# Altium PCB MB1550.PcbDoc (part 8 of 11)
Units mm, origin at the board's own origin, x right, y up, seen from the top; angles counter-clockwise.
Board outline 154.81 x 170.69 mm, 6 copper layers (Top Layer, Signal Layer 1, Signal Layer 2, Signal Layer 3, Signal Layer 4, Bottom Layer), stack 1.49 mm thick; 810 components, 633 nets, 2973 pads, 2150 vias.
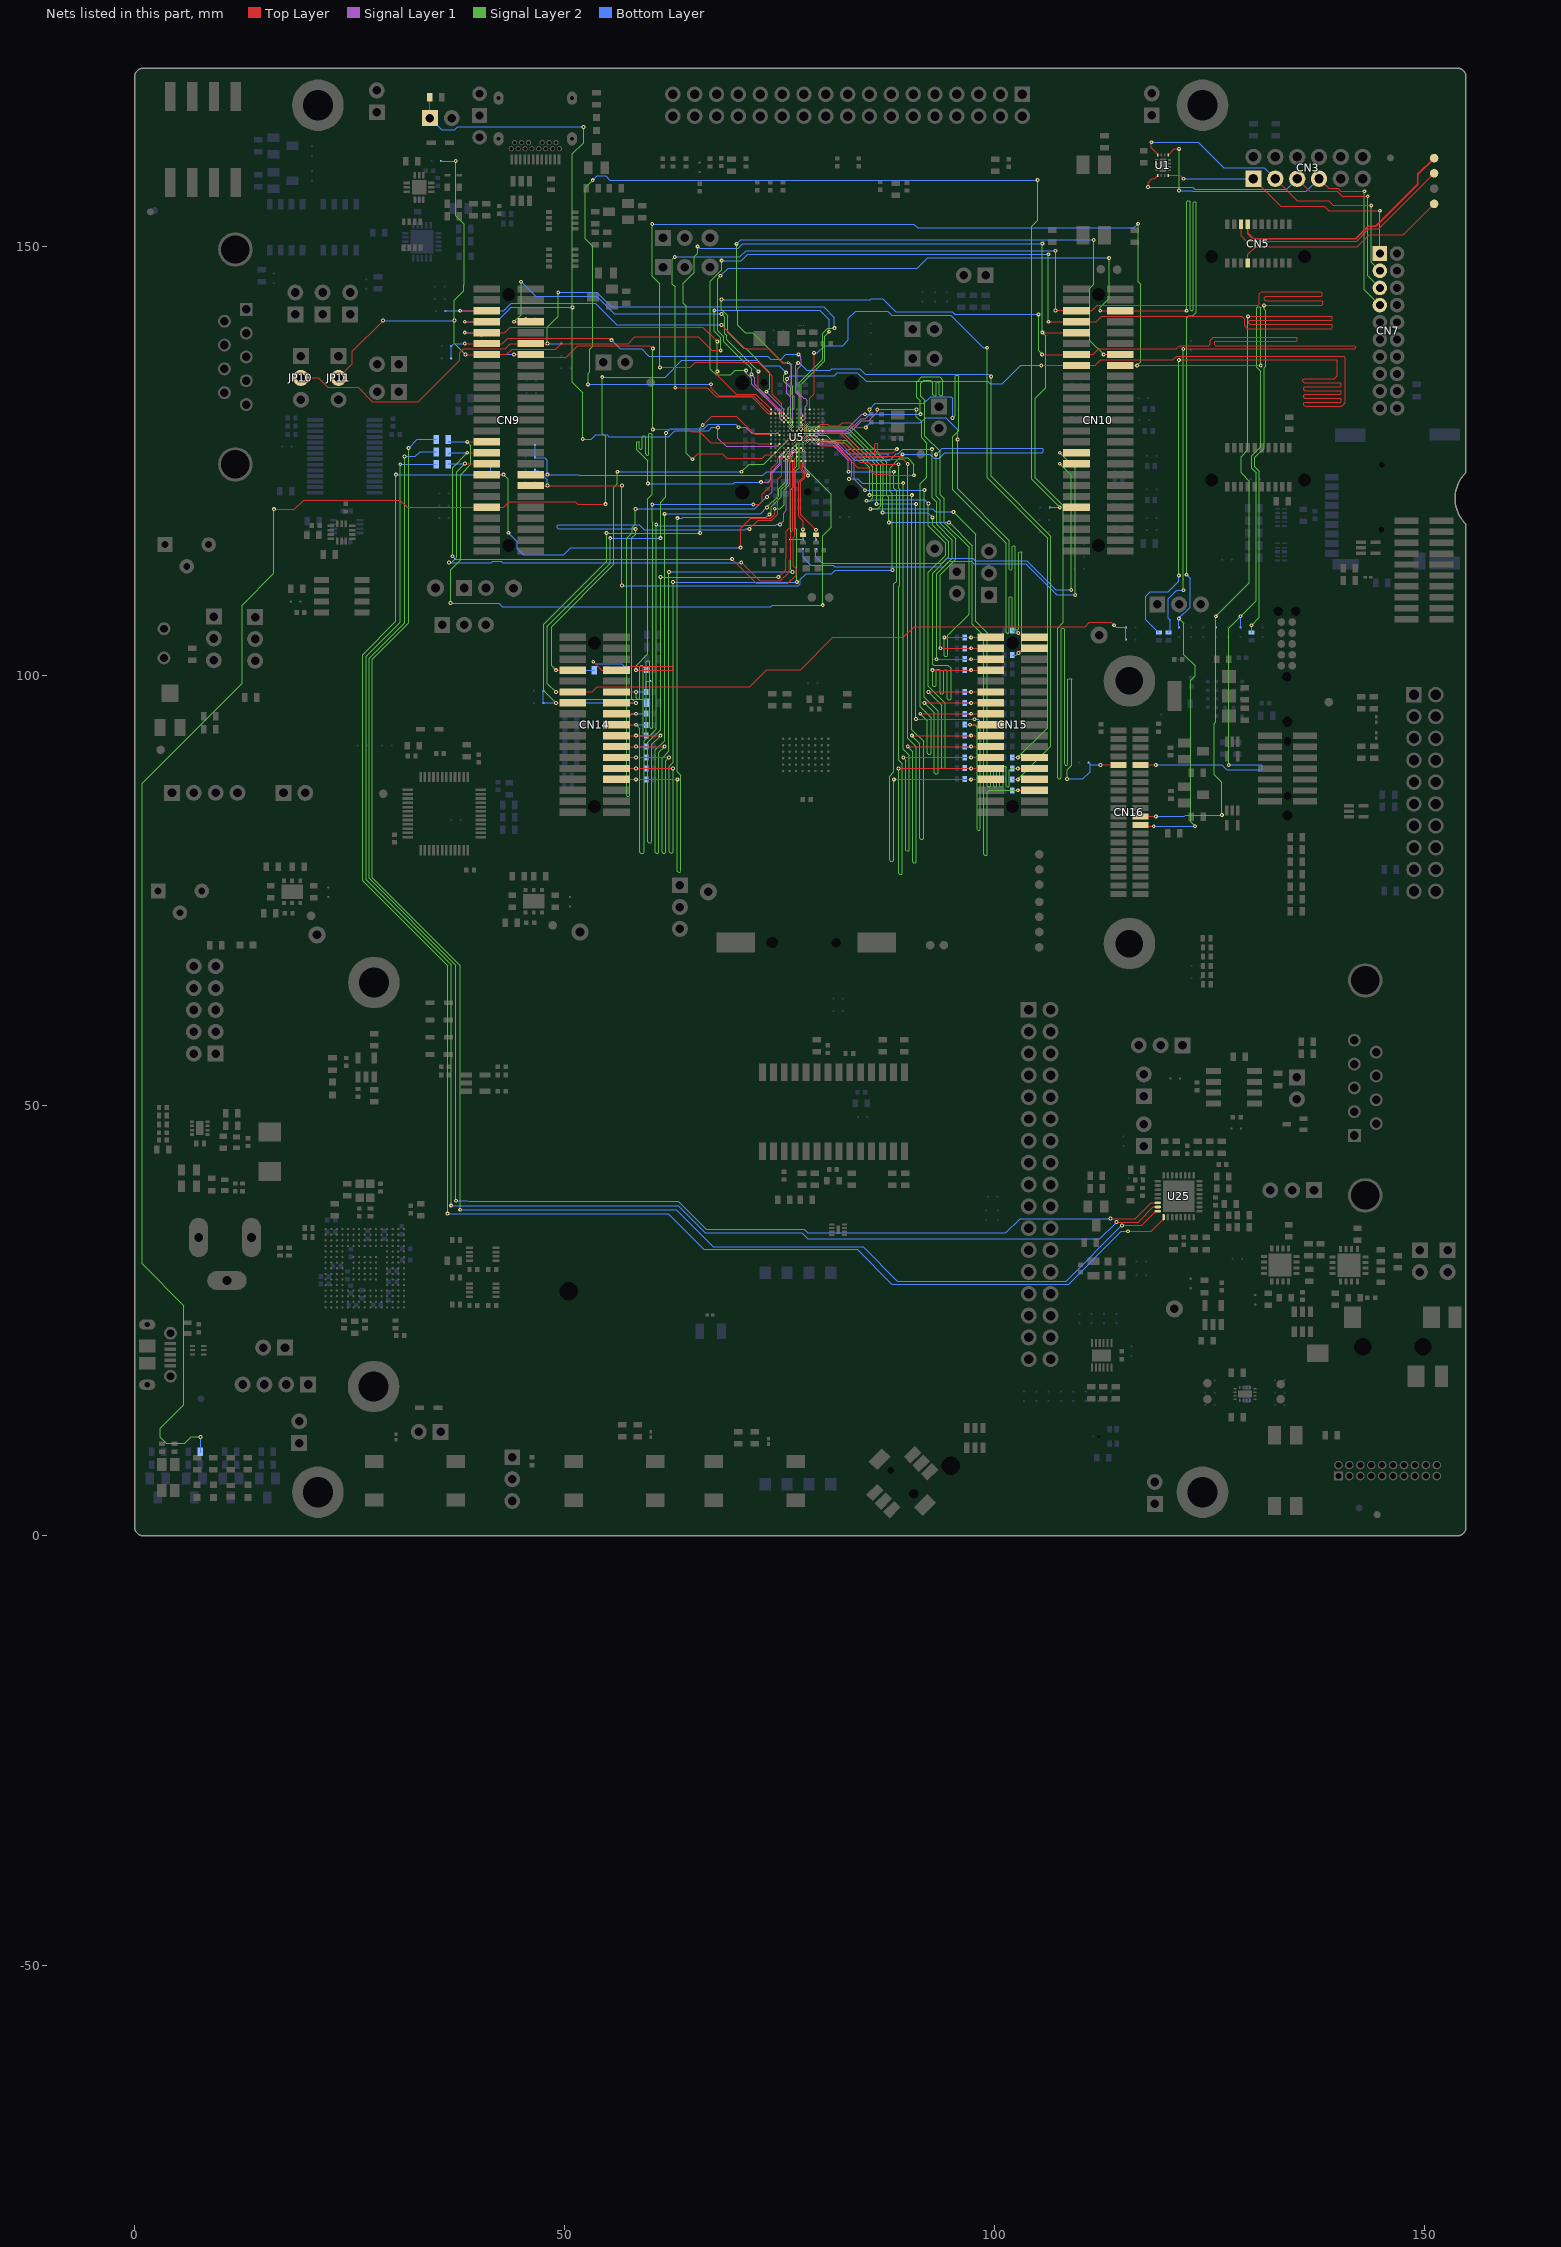
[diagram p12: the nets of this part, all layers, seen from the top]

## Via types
v1: diameter 0.45, hole 0.2, Top Layer to Bottom Layer, tented both sides, 1777 vias
v2: diameter 0.25, hole 0.1, Top Layer to Signal Layer 1, tented top, 344 vias
v3: diameter 0.25, hole 0.1, Signal Layer 1 to Signal Layer 2, 29 vias

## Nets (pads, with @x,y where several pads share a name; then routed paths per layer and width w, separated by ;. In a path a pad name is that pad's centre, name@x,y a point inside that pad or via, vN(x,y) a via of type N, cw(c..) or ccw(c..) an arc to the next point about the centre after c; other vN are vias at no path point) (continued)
PE3: CN14.8 R189.2 U5.D3 | length 81.7
  Top Layer w0.1: v1(53.325,101.65) 54.295,100.68 CN14.8@56.025,100.68 57.155,100.68 57.625,101.15 62.575,101.15 62.65,101.075 62.65,100.8 62.53,100.68 v1(58.295,100.68) ; v2(75.25,125.75) U5.D3@75.5,126
  Signal Layer 1 w0.08: v1(72.842,122.536) 73.686,122.536 73.95,122.8 73.95,123.65 75.035,124.735 75.035,125.434 75.25,125.649 v2(75.25,125.75)
  Signal Layer 2 w0.09: v1(58.295,100.68) 58.295,101.195 59.675,102.575 59.675,120.625 60.175,121.125 60.175,128.05 60.025,128.2 59.85,128.2 59.75,128.1 59.75,125.75 59.675,125.675 59.55,125.675 59.4,125.825 59.4,127.85 59.325,127.925 59.119,127.925 59.025,127.831 59.025,126.468 58.925,126.368 58.79,126.368 58.685,126.473 58.685,127.203 58.643,127.245 58.435,127.245 58.382,127.193 58.382,126.293 59.675,125 v1(59.675,122.372)
  Bottom Layer w0.1: v1(53.325,101.65) 53.525,101.45 56.625,101.45 56.925,101.15 59.025,101.15 59.475,100.7 R189.2@59.475,100.675 ; v1(59.675,122.372) 69.625,122.372 69.789,122.536 v1(72.842,122.536)
PE4: CN14.12 R191.1 SB105.1 U5.C2 | length 80.9
  Top Layer w0.08: 74.6,124.7 74.75,124.85 74.75,125.104 74.75,125.25 U5.C2@75,125.5
  Top Layer w0.1: CN14.12@56.025,98.14 v1(58.295,98.14) ; v1(71.925,119.95) 72.65,119.95 73,120.3 73,121.125 74.05,122.175 74.05,124.15 74.6,124.7
  Signal Layer 2 w0.09: v1(58.295,98.14) 58.295,97.451 58.446,97.3 58.625,97.3 58.75,97.425 58.75,101.096 58.876,101.221 59.02,101.221 59.15,101.091 59.15,100.55 ; 59.152,100.55 59.152,93.223 59.225,93.15 59.413,93.15 59.5,93.237 59.5,101.675 59.6,101.775 59.75,101.775 59.875,101.65 59.875,94.025 60,93.9 60.163,93.9 60.248,93.985 60.248,117.792 60.175,117.865 v1(60.175,119.95)
  Bottom Layer w0.1: v1(58.295,98.14) 59.465,98.14 R191.1@59.475,98.15 59.475,99.4 SB105.1@59.975,99.4 ; v1(60.175,119.95) v1(71.925,119.95)
PE5: CN14.14 R194.2 U5.D2 | length 85.3
  Top Layer w0.08: 74.8,119.1 74.8,122.875 75.25,123.325 75.25,125.25 U5.D2@75.5,125.5
  Top Layer w0.1: 74.775,118.8 74.8,118.825 74.8,119.1
  Top Layer w0.12: v1(71.475,117.1) 72.5,118.125 74.1,118.125 74.775,118.8
  Top Layer w0.127: CN14.14@56.025,96.87 v1(58.295,96.87)
  Signal Layer 2 w0.12: v1(58.25,117.1) 58.25,116.5 57.8,116.05 57.8,97.365 v1(58.295,96.87)
  Bottom Layer w0.12: v1(58.25,117.1) 49.25,117.1 49.125,117.225 49.125,117.45 49.275,117.6 58.688,117.6 59.258,117.03 70.972,117.03 71.042,117.1 v1(71.475,117.1) ; v1(58.295,96.87) 49.68,96.87 49.6,96.95 49.6,97.175 49.7,97.275 59.55,97.275 R194.2@59.55,96.9
PE6: CN14.16 R198.2 U5.E4 | length 70.3
  Top Layer w0.1: CN14.16@56.025,95.6 v1(58.295,95.6) ; v2(75.75,126.25) U5.E4@76,126.5
  Signal Layer 1 w0.08: v1(73.525,120.825) 74.15,121.45 74.15,123.617 75.2,124.667 75.2,125.346 75.5,125.646 75.5,125.854 75.5,126 v2(75.75,126.25)
  Signal Layer 2 w0.09: v1(58.225,119.425) 58.225,117.635 58.091,117.501 58.084,117.501 57.844,117.261 57.844,116.661 57.2,116.017 57.2,86.1 57.3,86 57.45,86 57.575,86.125 57.575,95.35 57.825,95.6 v1(58.295,95.6)
  Bottom Layer w0.1: v1(58.225,119.425) 72.125,119.425 v1(73.525,120.825) ; v1(58.295,95.6) 59.425,95.6 R198.2@59.475,95.65
PE7: CN15.15 R200.2 U5.L7 | length 69.3
  Top Layer w0.1: U5.L7@79,128 v2(79.25,127.75) ; v1(91.35,95.6) v1(97.271,95.6) CN15.15@99.541,95.6
  Signal Layer 1 w0.08: v2(79.25,127.75) 79.722,128.222 83.065,128.222 84.518,129.675 85.375,129.675 86.35,130.65 v1(86.35,131)
  Signal Layer 2 w0.09: v1(90.9,131) 90.9,130.165 91.508,129.557 91.508,127.702 92.125,127.085 92.125,123.1 91.35,122.325 91.35,96.4 92.6,95.15 92.6,91 92.5,90.9 92.25,90.9 92.142,91.008 92.142,94.808 v1(91.35,95.6)
  Bottom Layer w0.1: v1(86.35,131) v1(90.9,131) ; R200.2@96.525,95.6 v1(97.271,95.6)
PE8: CN15.13 R197.2 U5.K7 | length 68.5
  Top Layer w0.1: U5.K7@78.5,128 v2(78.75,127.75) ; v1(91.825,96.87) v1(97.271,96.87) CN15.13@99.541,96.87
  Signal Layer 1 w0.08: v2(78.75,127.75) 79,127.5 79.547,127.5 79.721,127.325 81.488,127.325 83.65,125.163 83.65,122.875 v1(84.925,121.6)
  Signal Layer 2 w0.09: v1(91.825,96.87) 92.992,95.703 92.992,88.733 93.075,88.65 93.35,88.65 93.45,88.75 93.45,95.875 91.825,97.5 v1(91.825,121.625)
  Bottom Layer w0.1: v1@84.925,121.625 v1(91.825,121.625) ; R197.2@96.53,96.87 v1(97.271,96.87)
  Bottom Layer w0.127: R197.2@96.525,96.875 R197.2@96.53,96.87
PE9: CN15.11 R193.2 U5.J7 | length 73.1
  Top Layer w0.1: v3(78,128) v2(78.25,127.75) ; v1(92.3,98.14) v1(97.271,98.14) CN15.11@99.541,98.14
  Signal Layer 1 w0.08: v3(78,128) v2(78.25,127.75)
  Signal Layer 2 w0.09: v3(78,128) 80.4,128 80.975,127.425 82.75,127.425 85.825,124.35 85.825,120.75 85.45,120.375 v1(85.1,120.375) ; v1(92.3,98.14) 93.842,96.598 93.842,89.325 93.917,89.25 94.2,89.25 94.275,89.325 94.275,96.825 92.3,98.8 92.3,112.044 94.299,114.043 94.299,115.451 92.3,117.45 v1(92.3,120.05)
  Bottom Layer w0.1: v1(85.1,120.375) 85.775,120.375 85.9,120.5 91.85,120.5 v1(92.3,120.05) ; R193.2@96.54,98.14 v1(97.271,98.14)
  Bottom Layer w0.127: R193.2@96.525,98.125 R193.2@96.54,98.14
PE10: CN15.7 R188.2 U5.H8 | length 70.7
  Top Layer w0.1: v3(77.5,128.5) v2(77.75,128.75) ; v1(92.775,100.68) v1(97.271,100.68) CN15.7@99.541,100.68
  Signal Layer 1 w0.08: v3(77.5,128.5) v2(77.75,128.75)
  Signal Layer 2 w0.08: v3(77.5,128.5) v2(77.75,128.75) 82.125,128.75
  Signal Layer 2 w0.09: 82.125,128.75 82.975,128.75 87.05,124.675 87.05,120.825 86.975,120.75 v1(86.975,119) ; v1(92.775,100.68) 92.775,98.879 92.877,98.777 93.102,98.777 93.225,98.9 93.225,100.7 93.325,100.8 93.55,100.8 93.65,100.7 93.65,98.004 93.74,97.915 93.965,97.915 94.075,98.025 94.075,100.65 94.175,100.75 94.4,100.75 94.5,100.65 94.5,97.35 94.6,97.25 94.85,97.25 94.925,97.325 94.925,100.875 94.575,101.225 92.925,101.225 92.775,101.375 92.775,111.964 94.691,113.88 94.691,115.63 92.775,117.546 v1(92.775,118.45)
  Bottom Layer w0.1: v1(86.975,119) 92.225,119 v1(92.775,118.45) ; R188.2@96.53,100.68 v1(97.271,100.68)
  Bottom Layer w0.127: R188.2@96.525,100.675 R188.2@96.53,100.68
PE11: CN15.5 R185.2 U5.M8 | length 71
  Top Layer w0.08: U5.M8@79.5,128.5 79.75,128.75 80.139,128.75 80.481,128.408 82.267,128.408
  Top Layer w0.1: 82.267,128.408 84.725,125.95 85.949,125.95 86.037,126.038 86.037,126.922 86.167,127.051 86.322,127.051 86.422,126.951 86.422,126.092 86.565,125.95 88.2,125.95 v1(88.625,126.375) ; v1(93.25,101.95) v1(97.271,101.95) CN15.5@99.541,101.95
  Signal Layer 2 w0.09: v1(92.725,126.375) 92.725,120.75 93.25,120.225 93.25,117.625 95.083,115.792 95.083,113.718 93.25,111.885 v1(93.25,101.95)
  Bottom Layer w0.1: v1(88.625,126.375) 82.875,126.375 82.725,126.225 82.725,126.025 82.9,125.85 87.55,125.85 87.65,125.75 87.65,125.575 87.55,125.475 83.75,125.475 83.65,125.375 83.65,125.167 83.725,125.092 87.802,125.092 88.56,125.85 88.785,125.85 89.31,126.375 v1(92.725,126.375) ; R185.2@96.525,101.95 v1(97.271,101.95)
PE12: CN15.3 R182.2 U5.N8 | length 71.4
  Top Layer w0.08: U5.N8@80,128.5 80.293,128.207 82.018,128.207
  Top Layer w0.1: 82.018,128.207 84.675,125.55 89.075,125.55 v1(89.3,125.775) ; v1(93.7,103.22) v1(97.271,103.22) CN15.3@99.541,103.22
  Signal Layer 2 w0.09: v1(93.2,125.775) 93.2,120.925 93.7,120.425 93.7,117.736 95.475,115.961 95.475,113.555 93.7,111.78 v1(93.7,103.22)
  Bottom Layer w0.1: v1(89.3,125.775) 92.475,125.775 92.95,125.3 93.55,125.3 94.225,125.975 105.55,125.975 105.675,126.1 105.675,126.325 105.525,126.475 93.9,126.475 v1(93.2,125.775) ; R182.2@96.57,103.22 v1(97.271,103.22)
  Bottom Layer w0.127: R182.2@96.525,103.175 R182.2@96.57,103.22
PE13: CN15.1 R180.2 U5.L8 | length 73.4
  Top Layer w0.1: U5.L8@79,128.5 v2(79.25,128.75) ; v1(94.15,104.49) v1(97.271,104.49) CN15.1@99.541,104.49
  Signal Layer 1 w0.08: v2(79.25,128.75) 79.445,128.555 82.68,128.555 84.562,130.437 v1(84.935,130.437)
  Signal Layer 2 w0.09: v1(91.375,130.45) 91.375,132 90.95,132.425 90.95,134.175 91.55,134.775 93.6,134.775 93.975,134.4 93.975,132.7 93.875,132.6 93.675,132.6 93.575,132.7 93.575,134.15 93.5,134.225 93.3,134.225 93.225,134.15 93.225,132.645 93.155,132.575 92.95,132.575 92.821,132.704 92.821,134.037 92.491,134.367 91.763,134.367 91.429,134.033 91.429,132.521 91.9,132.05 91.9,127.9 93.65,126.15 93.65,121.1 94.15,120.6 94.15,117.84 97.024,114.966 97.024,107.199 94.575,104.75 94.575,102.415 94.46,102.3 94.225,102.3 94.15,102.375 v1(94.15,104.49)
  Bottom Layer w0.1: v1(84.935,130.437) 91.362,130.437 v1(91.375,130.45) ; R180.2@96.535,104.49 v1(97.271,104.49)
  Bottom Layer w0.127: R180.2@96.525,104.5 R180.2@96.535,104.49
PE14: CN15.2 R175.2 U5.K8 | length 72
  Top Layer w0.1: U5.K8@78.5,128.5 v2(78.75,128.75) ; v1(102.75,105) 102.75,104.935 102.9,104.785 104.346,104.785 CN15.2@104.641,104.49
  Signal Layer 1 w0.08: v2(78.75,128.75) 79.11,128.39 82.94,128.39 84.475,129.925 84.95,129.925 85.45,130.425 v1(85.45,131)
  Signal Layer 2 w0.09: v1(95.1,130) 95.392,130.292 95.392,134.867 95.5,134.975 95.7,134.975 95.808,134.867 95.808,128.533 95.1,127.825 95.1,121.65 101.325,115.425 101.325,105.1 101.44,104.985 101.6,104.985 101.675,105.06 101.675,109.15 101.75,109.225 101.958,109.225 102.033,109.15 102.033,105.317 102.35,105 v1(102.75,105)
  Bottom Layer w0.1: v1(85.45,131) 86.138,131.688 91.766,131.688 92.545,132.468 94.901,132.468 95.1,132.269 v1(95.1,130) ; R175.2@102.025,105.3 102.385,105.3 102.685,105 v1(102.75,105)
PE15: CN15.4 R183.2 U5.M9 | length 74.2
  Top Layer w0.08: U5.M9@79.5,129 79.75,129.25 79.897,129.25 80.618,129.25 80.784,129.085
  Top Layer w0.1: 80.784,129.085 81.932,129.085 82.305,129.457 83.289,129.457 83.846,128.9 v1(85.025,128.9) ; v1(102.775,102.675) 102.775,102.8 102.9,102.925 104.346,102.925 CN15.4@104.641,103.22
  Signal Layer 2 w0.09: v1(95.7,127.5) 95.7,121.75 101.725,115.725 101.725,112.425 101.8,112.35 101.975,112.35 102.075,112.45 102.075,115.075 102.15,115.15 102.3,115.15 102.425,115.025 102.425,105.475 102.5,105.4 102.7,105.4 102.8,105.5 102.8,114.375 102.9,114.475 103.071,114.475 103.15,114.396 103.15,103.05 v1(102.775,102.675)
  Bottom Layer w0.1: v1(85.025,128.9) 85.547,129.422 91.347,129.422 91.965,130.04 94.314,130.04 95.7,128.654 95.7,127.508 v1@95.692,127.508 ; R183.2@102.025,102.425 102.525,102.425 v1(102.775,102.675)
PF0: CN14.18 R205.1 U5.E2 | length 80.6
  Top Layer w0.08: v2(75.75,125.25) U5.E2@76,125.5
  Top Layer w0.1: CN14.18@56.025,94.33 v1(58.295,94.33)
  Signal Layer 1 w0.08: v1(75.05,117.625) 75.45,118.025 75.45,118.95 75.75,119.25 v2(75.75,125.25)
  Signal Layer 2 w0.09: v1(58.295,94.33) 58.75,93.875 58.75,79.5 58.85,79.4 59.175,79.4 59.273,79.498 59.273,92.442 60.65,93.819 v1(60.65,117.625)
  Bottom Layer w0.1: v1(58.295,94.33) R205.1@59.47,94.33 ; v1(60.65,117.625) 60.832,117.443 70.8,117.443 70.87,117.513 74.541,117.513 74.653,117.625 v1(75.05,117.625)
  Bottom Layer w0.127: R205.1@59.47,94.33 R205.1@59.475,94.325
PF1: CN14.20 R208.1 U5.F3 | length 79.9
  Top Layer w0.08: 76.25,119.025 76.25,125.75 U5.F3@76.5,126
  Top Layer w0.1: CN14.20@56.025,93.06 v1(58.295,93.06) v1(61.15,93.06) ; v1(74.85,111.5) 75.682,112.332 75.682,113.591 75.775,113.685 75.775,116.825 76.25,117.3 76.25,119.025
  Signal Layer 2 w0.09: v1(61.15,93.06) 60.148,92.058 60.148,80.723 60.05,80.625 59.775,80.625 59.675,80.725 59.675,92.275 61.15,93.75 v1(61.15,111.5)
  Bottom Layer w0.1: v1(58.295,93.06) 59.46,93.06 R208.1@59.475,93.075 ; v1(61.15,111.5) v1(74.85,111.5)
PF2: CN14.22 R214.1 U5.F4 | length 80
  Top Layer w0.1: CN14.22@56.025,91.79 v1(58.295,91.79) v1(61.625,91.79) ; v2(76.25,126.25) U5.F4@76.5,126.5
  Signal Layer 1 w0.08: v3(76,126) v2(76.25,126.25)
  Signal Layer 2 w0.08: 75.7,122.569 75.7,125.7 v3(76,126)
  Signal Layer 2 w0.09: v1(61.625,91.79) 60.948,91.113 60.948,79.498 60.825,79.375 60.65,79.375 60.55,79.475 60.55,91.4 61.625,92.475 v1(61.625,118.85) ; v1(73.525,119.6) 74.9,120.975 74.9,121.769 75.7,122.569
  Bottom Layer w0.1: v1(58.295,91.79) 59.465,91.79 R214.1@59.475,91.8 ; v1(61.625,118.85) 72.775,118.85 v1(73.525,119.6)
PF3: CN14.24 R218.1 U5.G5 | length 82.2
  Top Layer w0.1: CN14.24@56.025,90.52 v1(58.295,90.52) v1(62.125,90.52) ; v2(76.75,126.75) v3(77,127)
  Signal Layer 1 w0.08: v2(76.75,126.75) v3(77,127)
  Signal Layer 2 w0.08: 76.262,121.45 76.262,121.637 76.6,121.975 76.6,123.975 77,124.375 v3(77,127)
  Signal Layer 2 w0.09: v1(62.125,90.52) 61.748,90.143 61.748,79.523 61.625,79.4 61.45,79.4 61.35,79.5 61.35,90.45 62.125,91.225 v1(62.125,112.1) ; 76.262,121.45 76.262,112.338 v1(76.5,112.1)
  Bottom Layer w0.1: v1(58.295,90.52) R218.1@59.47,90.52 ; v1(62.125,112.1) v1(76.5,112.1)
  Bottom Layer w0.127: R218.1@59.47,90.52 R218.1@59.475,90.525
PF4: CN14.26 R223.1 U5.G6 | length 81.6
  Top Layer w0.1: CN14.26@56.025,89.25 v1(58.295,89.25) v1(62.6,89.25) ; v2(76.75,127.25) v3(77,127.5)
  Signal Layer 1 w0.08: v2(76.75,127.25) v3(77,127.5)
  Signal Layer 2 w0.08: 76.825,122.7 76.825,123.8 77.25,124.225 77.25,127.25 v3(77,127.5)
  Signal Layer 2 w0.09: v1(62.6,89.25) 62.6,79.55 62.5,79.45 62.25,79.45 62.15,79.55 62.15,89.5 62.6,89.95 v1(62.6,110.925) ; 76.825,122.7 76.825,117.2 77,117.025 v1(77,110.925)
  Bottom Layer w0.1: v1(58.295,89.25) R223.1@59.475,89.25 ; v1(62.6,110.925) v1(77,110.925)
PF5: CN14.28 R227.1 U5.G4 | length 80.7
  Top Layer w0.1: CN14.28@56.025,87.98 v1(58.295,87.98) v1(63.1,87.98) ; v2(76.75,126.25) U5.G4@77,126.5
  Signal Layer 1 w0.08: v3(76.1,125.375) 76.1,125.747 ; 76.101,125.748 76.102,125.748 76.604,126.25 v2(76.75,126.25)
  Signal Layer 2 w0.08: 75.2,121.45 75.2,121.7 75.925,122.425 75.925,125.2 v3(76.1,125.375)
  Signal Layer 2 w0.09: v1(63.1,87.98) 63.1,77.315 63.24,77.175 63.41,77.175 63.525,77.29 63.525,88.45 63.1,88.875 v1(63.1,118.35) ; v1@73.825,118.8 74,118.975 74,119.667 75.2,120.867 75.2,121.45
  Signal Layer 2 w0.102: v1(73.8,118.775) v1@73.825,118.8
  Bottom Layer w0.1: v1(58.295,87.98) R227.1@59.47,87.98 ; v1(63.1,118.35) 63.65,118.35 63.733,118.433 73.458,118.433 v1(73.8,118.775)
  Bottom Layer w0.127: R227.1@59.47,87.98 R227.1@59.475,87.975
PF6: CN9.29 R153.1 U5.H6 | length 89.8
  Top Layer w0.08: v3(77.5,127.5) v2(77.75,127.25)
  Top Layer w0.127: v1(38.673,127.225) CN9.29@40.943,127.225
  Signal Layer 1 w0.08: v3(77.5,127.5) v2(77.75,127.25)
  Signal Layer 2 w0.08: v3(77.5,127.5) v2(77.75,127.25) 77.75,127.104 ; 77.75,126.896 77.75,124.4 81,121.15 ; 77.75,126.896 77.75,127.103
  Signal Layer 2 w0.1: 81,118.8 81,121.15
  Signal Layer 2 w0.12: v1(36.725,108.475) 36.725,112.375 37.892,113.542 37.892,123.392 39.099,124.599 39.099,126.799 v1(38.673,127.225) ; v1(80.012,108.238) 80.026,108.251 80.026,116.301 81,117.275 81,118.8
  Bottom Layer w0.12: R153.1@36.45,127.225 v1(38.673,127.225) ; v1(36.725,108.475) 42.327,108.475 42.752,108.05 73.95,108.05 74.137,108.238 v1(80.012,108.238)
PF7: CN9.31 R154.1 U5.G2 | length 73
  Top Layer w0.08: 76.75,119.05 76.75,125.25 U5.G2@77,125.5
  Top Layer w0.1: 76.75,118.8 76.75,119.05
  Top Layer w0.12: v1(69.475,113.6) 72.3,110.775 75.95,110.775 76.905,111.73 76.905,112.486 76.6,112.791 76.6,116.075 76.75,116.225 76.75,118.8
  Top Layer w0.127: v1(38.673,125.955) CN9.31@40.943,125.955
  Signal Layer 2 w0.12: v1(36.955,113.925) 36.955,124.237 v1(38.673,125.955)
  Bottom Layer w0.12: R154.1@36.45,125.775 36.63,125.955 v1(38.673,125.955) ; v1(36.955,113.925) 37.28,113.6 v1(69.475,113.6)
PF8: CN9.33 R157.1 U5.F1 | length 71.1
  Top Layer w0.08: 76.5,119.075 U5.F1@76.5,125
  Top Layer w0.1: 76.5,118.8 76.5,119.075
  Top Layer w0.12: v1(70.525,113.2) 72.675,111.05 75.075,111.05 76.095,112.07 76.095,113.386 76.275,113.566 76.275,116.725 76.5,116.95 76.5,118.8
  Top Layer w0.127: v1(38.4,124.7) 40.928,124.7 CN9.33@40.943,124.685
  Signal Layer 2 w0.12: v1(36.55,113.2) 36.858,113.2 37.475,113.817 37.475,123.775 v1(38.4,124.7)
  Bottom Layer w0.12: R157.1@36.45,124.625 36.525,124.7 v1(38.4,124.7) ; v1(36.55,113.2) 36.555,113.195 41.47,113.195 41.635,113.36 42.635,113.36 42.8,113.195 70.52,113.195 v1(70.525,113.2)
PF9: CN9.35 SB59.1 SB62.1 U5.G3 | length 57.2
  Top Layer w0.08: 74.4,118.8 74.425,118.825 v1(74.425,119.45) ; U5.G3@77,126 v2(77.25,126.25)
  Top Layer w0.102: 73.55,118.365 73.965,118.365 74.4,118.8
  Top Layer w0.12: v1(70.45,114.925) 70.45,117.175 71.64,118.365 73.55,118.365
  Top Layer w0.127: CN9.35@40.943,123.415 v1(42.889,123.415)
  Signal Layer 1 w0.08: v3(76.357,125.645) 76.45,125.738 76.45,125.812 76.638,126 77,126 v2(77.25,126.25)
  Signal Layer 2 w0.08: 75.55,121.45 75.55,121.675 76.15,122.275 76.15,124.797 76.357,125.005 v3(76.357,125.645)
  Signal Layer 2 w0.1: v1(74.425,119.45) 75.075,119.45 75.55,119.925 75.55,121.45
  Signal Layer 2 w0.12: v1(42.889,123.415) 43.45,122.854 43.45,116.675 43.425,116.65 v1(43.45,116.65)
  Bottom Layer w0.12: SB59.1@41.417,124.864 SB62.1@41.417,123.414 42.888,123.414 v1(42.889,123.415) ; v1(43.45,116.65) 44.51,115.59 44.51,114.778 45.196,114.092 49.892,114.092 50.725,114.925 v1(70.45,114.925)
PF10: CN9.36 SB55.1 SB58.1 U5.H4 | length 40.9
  Top Layer w0.08: U5.H4@77.5,126.5 v2(77.75,126.25)
  Top Layer w0.127: CN9.36@46.043,123.415 v1(47.989,123.415)
  Signal Layer 1 w0.08: v2(77.75,126.25) 78,126 78,125.854 78,123.9 78.275,123.625 v1(78.275,123.325)
  Bottom Layer w0.1: 66.725,123.317 73.026,123.317 73.469,123.76 77.84,123.76 v1(78.275,123.325)
  Bottom Layer w0.12: SB55.1@46.55,126.875 SB58.1@46.55,125.4 47.7,125.4 47.989,125.111 v1(47.989,123.415) 51.61,123.415 51.708,123.317 66.725,123.317
PF11: CN9.38 SB60.1 U5.M5 | length 86.9
  Top Layer w0.08: U5.M5@79.5,127 79.75,126.75 81.525,126.75 84.075,124.2 85.275,124.2 86,123.475 86.825,123.475
  Top Layer w0.12: v1(47.989,122.145) v1(56.663,122.145) ; 86.825,123.475 87.55,123.475 87.68,123.345 v1(90.605,123.345)
  Top Layer w0.127: CN9.38@46.043,122.145 v1(47.989,122.145)
  Signal Layer 2 w0.12: v1(56.663,110.512) v1(56.663,122.145) ; v1(88.116,112.316) 88.116,121.199 87.874,121.442 87.874,122.246 87.87,122.25 87.87,124.243 88.977,125.35 89.905,125.35 90.605,124.65 v1(90.605,123.345)
  Bottom Layer w0.12: 46.41,123.848 46.952,123.848 47.989,122.811 v1(47.989,122.145) ; v1(56.663,110.512) 77.171,110.512 77.414,110.754 77.414,111.245 78.084,111.916 81.066,111.916 81.466,112.316 v1(88.116,112.316)
PF12: CN15.27 R225.1 U5.K6 | length 79.8
  Top Layer w0.1: U5.K6@78.5,127.5 v2(78.75,127.25) ; v1(88.275,87.98) v1(97.271,87.98) CN15.27@99.541,87.98
  Signal Layer 1 w0.08: v2(78.75,127.25) 79,127 79.485,127 79.57,126.915 81.185,126.915 83,125.1 v1(83,123.75)
  Signal Layer 2 w0.09: v1(88.275,87.98) 88.275,78.55 88.175,78.45 87.875,78.45 87.775,78.55 87.775,88.35 88.275,88.85 88.275,110.7 88.591,111.016 88.591,121.534 88.275,121.85 v1(88.275,123.75)
  Bottom Layer w0.1: v1(83,123.75) v1(88.275,123.75) ; R225.1@96.545,87.98 v1(97.271,87.98)
  Bottom Layer w0.127: R225.1@96.525,88 R225.1@96.545,87.98
PF13: CN15.25 R221.1 U5.M6 | length 82.7
  Top Layer w0.08: U5.M6@79.488,127.505 79.497,127.496 79.743,127.25 81.903,127.25 84.303,124.85 85.375,124.85 85.6,124.625 86.825,124.625
  Top Layer w0.1: 86.825,124.625 v1(88.825,124.625) ; v1(88.825,89.25) v1(97.271,89.25) CN15.25@99.541,89.25
  Signal Layer 2 w0.09: v1(88.825,89.25) 88.825,77.05 88.95,76.925 89.225,76.925 89.273,76.973 89.273,89.777 88.825,90.225 88.825,110.375 88.983,110.533 88.983,121.696 88.825,121.854 v1(88.825,124.625)
  Bottom Layer w0.1: R221.1@96.55,89.25 v1(97.271,89.25)
  Bottom Layer w0.127: R221.1@96.525,89.275 R221.1@96.55,89.25
PF14: CN15.23 R219.1 U5.L6 | length 79.5
  Top Layer w0.1: U5.L6@79,127.5 v2(79.25,127.25) ; v1(89.375,90.52) v1(97.271,90.52) CN15.23@99.541,90.52
  Signal Layer 1 w0.08: v2(79.25,127.25) 79.528,127.25 79.653,127.125 81.322,127.125 83.4,125.047 83.4,123.225 v1(83.075,122.9)
  Signal Layer 2 w0.09: v1(89.375,90.52) 89.675,90.22 89.675,79.725 89.75,79.65 90,79.65 90.073,79.723 90.073,90.777 89.375,91.475 v1(89.375,122.425)
  Bottom Layer w0.1: v1(83.075,122.9) 83.099,122.924 84.102,122.924 84.103,122.925 84.603,122.425 v1(89.375,122.425) ; R219.1@96.53,90.52 v1(97.271,90.52)
  Bottom Layer w0.127: R219.1@96.525,90.525 R219.1@96.53,90.52
PF15: CN15.21 R215.1 U5.N6 | length 82.3
  Top Layer w0.1: U5.N6@80,127.5 80.003,127.497 82.153,127.497 84.475,125.175 89.375,125.175 v1(89.9,124.65) ; v1(89.9,91.79) v1(97.271,91.79) CN15.21@99.541,91.79
  Signal Layer 2 w0.09: v1(89.9,91.79) 90.475,91.215 90.475,78.375 90.575,78.275 90.825,78.275 90.898,78.348 90.898,91.777 89.9,92.775 v1(89.9,124.65)
  Bottom Layer w0.1: R215.1@96.541,91.79 v1(97.271,91.79)
  Bottom Layer w0.127: R215.1@96.525,91.775 R215.1@96.541,91.79
PG0: CN15.19 R209.1 U5.J6 | length 80.9
  Top Layer w0.1: v3(78,127.5) v2(78.25,127.25) ; v1(90.375,93.06) v1(97.271,93.06) CN15.19@99.541,93.06
  Signal Layer 1 w0.08: v3(78,127.5) v2(78.25,127.25)
  Signal Layer 2 w0.09: v3(78,127.5) 80.4,127.5 80.8,127.1 82.55,127.1 85.45,124.2 v1(85.45,121.025) ; v1(90.375,93.06) 91.3,92.135 91.3,81.125 91.4,81.025 91.65,81.025 91.75,81.125 91.75,92.4 90.375,93.775 v1(90.375,121.025)
  Bottom Layer w0.1: v1(85.45,121.025) v1(90.375,121.025) ; R209.1@96.535,93.06 v1(97.271,93.06)
  Bottom Layer w0.127: R209.1@96.525,93.05 R209.1@96.535,93.06
PG1: CN15.17 R203.1 U5.H7 | length 81.5
  Top Layer w0.08: v3(77.5,128) v2(77.75,127.75)
  Top Layer w0.1: v1(90.85,94.988) 90.863,94.975 v1(97.65,94.975) ; v1(97.125,94.325) 99.536,94.325 CN15.17@99.541,94.33
  Signal Layer 1 w0.08: v3(77.5,128) v2(77.75,127.75)
  Signal Layer 2 w0.08: v3(77.5,128) 77.75,128.25 82.1,128.25
  Signal Layer 2 w0.09: 82.1,128.25 82.45,128.25 86.275,124.425 v1(86.275,120) ; v1(90.85,94.988) 90.85,119.975 v1(90.875,120) ; v1@97.275,94.325 97.675,94.325 97.975,94.025 97.975,82.15 98.05,82.075 98.275,82.075 98.348,82.148 98.348,94.702 98.074,94.976 ; v1(97.65,94.975) 98.074,94.975
  Bottom Layer w0.1: v1(86.275,120) v1(90.875,120) ; R203.1@96.55,94.325 v1(97.125,94.325)
  Bottom Layer w0.127: R203.1@96.525,94.35 R203.1@96.55,94.325
PG2: CN15.24 R217.1 U5.K13 | length 86.8
  Top Layer w0.08: U5.K13@78.5,131 78.5,132.3 79.01,132.81 79.01,133.184 79,133.194 79,136.85
  Top Layer w0.1: 79,136.85 v1(79,137.575) ; v1(102.695,90.52) CN15.24@104.641,90.52
  Signal Layer 2 w0.09: v1(99.125,138.175) 99.125,123.025 106.15,116 106.15,93.975 v1(102.695,90.52)
  Bottom Layer w0.1: v1(79,137.575) 79.375,137.575 80.225,138.425 82.325,138.425 82.989,139.089 82.989,141.579 83.852,142.442 84.699,142.442 84.704,142.437 85.046,142.437 85.051,142.442 87.548,142.442 88.028,141.962 94.913,141.962 98.7,138.175 v1(99.125,138.175) ; R217.1@102.03,90.52 v1(102.695,90.52)
  Bottom Layer w0.127: R217.1@102.025,90.525 R217.1@102.03,90.52
PG3: CN15.26 R222.1 U5.J8 | length 82.2
  Top Layer w0.1: v3(78,128.5) v2(78.25,128.75) ; v1(102.695,89.25) CN15.26@104.641,89.25
  Signal Layer 1 w0.08: v3(78,128.5) v2(78.25,128.75)
  Signal Layer 2 w0.09: v3(78,128.5) 82.725,128.5 86.75,124.475 86.75,119.775 86.4,119.425 v1(85.55,119.425) ; v1(95.2,119.075) 97.808,116.467 97.808,106.342 99.152,104.998 99.152,87.223 99.25,87.125 99.45,87.125 99.55,87.225 99.55,89.4 99.625,89.475 99.85,89.475 99.9,89.425 99.9,87.179 99.967,87.112 100.162,87.112 100.25,87.2 100.25,89.375 100.325,89.45 100.542,89.45 100.6,89.392 100.6,87.2 100.688,87.112 100.862,87.112 100.975,87.225 100.975,89.404 101.046,89.475 101.3,89.475 101.375,89.4 101.375,87.2 101.463,87.112 101.637,87.112 101.725,87.2 101.725,89.065 101.91,89.25 v1(102.695,89.25)
  Bottom Layer w0.1: v1(85.55,119.425) 92.8,119.425 93.15,119.075 v1(95.2,119.075) ; R222.1@102.025,89.25 v1(102.695,89.25)
PG4: CN15.28 R226.1 U5.H11 | length 84.2
  Top Layer w0.1: U5.H11@77.5,130 v2(77.75,130.25) ; v1(102.695,87.98) CN15.28@104.641,87.98
  Signal Layer 1 w0.08: v1(77.15,136.4) 76.88,136.13 76.88,132.987 77.375,132.492 77.375,130.712 77.75,130.337 v2(77.75,130.25)
  Signal Layer 2 w0.09: v1@99.6,134.825 v1(99.596,134.821) 99.596,123.229 106.55,116.275 106.55,91.835 v1(102.695,87.98)
  Bottom Layer w0.1: v1(77.15,136.4) 77.3,136.4 78.144,135.556 80.9,135.556 81.079,135.735 84.315,135.735 84.963,135.087 99.33,135.087 v1(99.596,134.821) ; R226.1@102.03,87.98 v1(102.695,87.98)
  Bottom Layer w0.127: R226.1@102.025,87.975 R226.1@102.03,87.98
PG5: CN15.30 R229.1 U5.J9 | length 80.3
  Top Layer w0.1: v3(78,129) v2(78.25,129.25) ; v1(102.695,86.71) CN15.30@104.641,86.71
  Signal Layer 1 w0.08: v3(78,129) v2(78.25,129.25)
  Signal Layer 2 w0.09: v3(78,129) 83.3,129 87.45,124.85 87.45,121.025 87.7,120.775 v1(87.7,117.85) ; v1(94.7,117.85) 97.416,115.134 97.416,106.041 98.75,104.707 98.75,79.25 98.85,79.15 99.075,79.15 99.125,79.2 99.125,86.475 99.36,86.71 v1(102.695,86.71)
  Bottom Layer w0.1: v1(87.7,117.85) v1(94.7,117.85) ; R229.1@102.035,86.71 v1(102.695,86.71)
  Bottom Layer w0.127: R229.1@102.025,86.7 R229.1@102.035,86.71
PG6: CN9.11 SB33.1 SB38.1 U5.H10 | length 52.5
  Top Layer w0.08: U5.H10@77.5,129.5 v2(77.75,129.75)
  Top Layer w0.12: v1(38.38,138.655) CN9.11@40.943,138.655 42.755,138.655 43.4,139.3 55.2,139.3 v1(55.45,139.05)
  Signal Layer 1 w0.08: 77.425,136.85 77.5,136.775 77.5,136.143 77.045,135.688 77.045,133.055 77.821,132.279 77.953,132.279 78.215,132.017 78.215,131.522 78,131.307 78,130.853 78,130.646 78,130 v2(77.75,129.75)
  Signal Layer 1 w0.102: v1(77.2,137.4) 77.425,137.175 77.425,136.85
  Bottom Layer w0.12: SB38.1@36.8,136.95 SB33.1@36.8,138.375 37.08,138.655 v1(38.38,138.655) ; v1(55.45,139.05) 56.475,138.025 58.975,138.025 59.8,137.2 73.6,137.2 73.95,136.85 75.175,136.85 75.725,137.4 v1(77.2,137.4)
PG7: CN9.12 JP10.2 SB31.1 U5.G8 | length 90.7
  Top Layer w0.08: v3(77,128.5) v2(77.25,128.75)
  Top Layer w0.12: JP10.2@19.325,134.66 21.315,134.66 22.425,133.55 25.985,133.55 27.635,131.9 32.975,131.9 37.775,136.7 37.775,137.575 38.25,138.05 43.075,138.05 43.68,138.655 CN9.12@46.043,138.655
  Top Layer w0.127: CN9.12@46.043,138.655 v1(47.989,138.655)
  Signal Layer 1 w0.08: v3(77,128.5) v2(77.25,128.75)
  Signal Layer 2 w0.08: v3(77,128.5) v2(77.25,128.75) 77.25,128.896 77.25,129.104 77.25,134.1
  Signal Layer 2 w0.1: 77.25,134.1 80,136.85
  Signal Layer 2 w0.12: v1(47.989,138.655) 47.989,140.564 49.25,141.825 v1(49.25,144.6) ; 80,136.85 80,139.848 80.602,140.45 v1(81.375,140.45)
  Bottom Layer w0.12: v1(47.989,138.655) 49.58,138.655 SB31.1@49.6,138.675 ; v1(49.25,144.6) 53.725,144.6 55.402,142.923 80.126,142.923 81.375,141.674 v1(81.375,140.45)
PG8: CN9.13 JP11.2 SB11.1 U5.H9 | length 107.2
  Top Layer w0.08: v3(77.5,129) v2(77.75,129.25)
  Top Layer w0.12: JP11.2@23.7,134.66 25.32,136.28 25.32,137.78 v1(28.875,141.335) ; v1(38.475,137.375) 40.933,137.375 CN9.13@40.943,137.385 43.285,137.385 43.892,137.992 48.967,137.992 49.62,138.645 57.372,138.645 58.157,139.43 65.544,139.43 67.104,137.87 v1(68.155,137.87)
  Signal Layer 1 w0.08: v3(77.5,129) v2(77.75,129.25)
  Signal Layer 2 w0.1: v3(77.5,129) 77.5,133.928 80.24,136.668 80.24,136.85
  Signal Layer 2 w0.12: v1(37.325,159.875) 37.325,153.525 38.3,152.55 38.3,145.5 38.268,145.468 38.268,144.814 37.175,143.721 37.175,138.675 37.325,138.525 v1(38.475,137.375) ; v1@67.388,142.505 67.388,140.079 68.155,139.313 v1(68.155,137.87) ; 80.24,136.85 80.24,139.515 v1(80.75,140.025)
  Bottom Layer w0.12: v1(28.875,141.335) v1(37.175,141.335) ; SB11.1@35.6,159.875 v1(37.325,159.875) ; v1(67.4,142.518) 79.657,142.518 80.75,141.425 v1(80.75,140.025)
PG9: CN14.13 SB107.1 SB108.1 U5.A7 | length 61.1
  Top Layer w0.08: 66.725,129.85 67.1,130.225 69.96,130.225 72.1,128.085 73.915,128.085 U5.A7@74,128
  Top Layer w0.12: v1(66.05,129.175) 66.725,129.85
  Top Layer w0.127: v1(48.979,96.87) CN14.13@50.925,96.87
  Signal Layer 2 w0.12: v1(48.979,96.87) 47.55,98.299 47.55,106.025 54.875,113.35 v1(54.875,116.625) ; v1(65.755,116.625) 65.755,128.88 v1(66.05,129.175)
  Bottom Layer w0.12: SB107.1@47.525,98.275 SB108.1@47.525,96.85 47.545,96.87 v1(48.979,96.87) ; v1(54.875,116.625) v1(65.755,116.625)
PG10: CN14.11 SB102.1 SB103.1 U5.C7 | length 125.1
  Top Layer w0.08: v2(74.75,128.25) U5.C7@75,128
  Top Layer w0.12: CN14.11@50.72,98.14 CN14.11@50.925,98.14 53.19,98.14 53.8,98.75 71.525,98.75 73.525,100.75 77.425,100.75 81.168,104.493 89.368,104.493 90.625,105.75 110.525,105.75 111,106.225 113.575,106.225 v1(113.9,105.9)
  Top Layer w0.127: v1(48.979,98.14) CN14.11@50.72,98.14
  Signal Layer 1 w0.08: v1(70.225,128.925) 71.05,128.925 71.725,128.25 73.925,128.25 v2(74.75,128.25)
  Signal Layer 2 w0.12: v1(48.979,98.14) 48,99.119 48,105.8 55.3,113.1 v1(55.3,116.025) ; v1(61.15,116.025) 61.15,120.225 61.775,120.85 v1(61.775,128.25)
  Bottom Layer w0.1: 66.725,129.275 69.875,129.275 v1(70.225,128.925)
  Bottom Layer w0.12: v1(55.3,116.025) v1(61.15,116.025) ; v1(61.775,128.25) 62.275,128.75 66.198,128.75 66.723,129.275 66.725,129.275 ; v1(113.9,105.9) 114.15,105.65 SB102.1@115.275,105.65 SB103.1@115.275,104.225
PG12: CN14.7 R187.1 U5.E6 | length 55
  Top Layer w0.08: v2(75.75,127.25) v3(76,127.5)
  Top Layer w0.127: v1(48.979,100.68) CN14.7@50.925,100.68
  Signal Layer 1 w0.08: v2(75.75,127.25) v3(76,127.5)
  Signal Layer 2 w0.08: 71.45,124.65 73.15,124.65 v3(76,127.5)
  Signal Layer 2 w0.1: v1(70.55,123.75) 71.45,124.65
  Signal Layer 2 w0.12: v1(48.979,100.68) 48.475,101.184 48.475,105.725 55.725,112.975 55.725,121.95 56.125,122.35 v1(56.125,123.75)
  Bottom Layer w0.1: 66.725,123.75 v1(70.55,123.75)
  Bottom Layer w0.12: v1(48.979,100.68) 48.984,100.675 R187.1@53.425,100.675 ; v1(56.125,123.75) 56.13,123.755 66.725,123.755
PG15: CN9.14 SB35.1 U5.A5 | length 43.7
  Top Layer w0.08: 66.8,127.3 66.95,127.15 72.275,127.15 72.425,127 U5.A5@74,127
  Top Layer w0.1: 66.725,127.375 66.8,127.3
  Top Layer w0.12: CN9.14@46.043,137.385 46.043,137.07 50.181,137.07 51.516,138.405 59.92,138.405 v1(60.25,138.075) ; v1(60.25,128.675) 64.45,128.675 64.75,128.375 65.725,128.375 66.725,127.375
  Top Layer w0.127: v1(44.097,137.385) CN9.14@46.043,137.385
  Signal Layer 2 w0.12: v1(60.25,128.675) v1(60.25,138.075)
  Bottom Layer w0.12: SB35.1@41.4,137.4 41.415,137.385 v1(44.097,137.385)
PH0: CN10.31 SB89.1 | length 54.2
  Top Layer w0.127: v1(107.577,125.955) CN10.31@109.523,125.955
  Signal Layer 2 w0.12: v1(107.577,125.955) 109.375,124.157 v1(109.375,109.425)
  Bottom Layer w0.12: SB89.1@77.725,114.775 77.725,113.8 78.64,112.885 81.24,112.885 81.4,112.725 94.09,112.725 94.69,113.325 97.3,113.325 97.56,113.065 103.61,113.065 107.25,109.425 v1(109.375,109.425)
PH0-OSC_IN: R25.1 SB89.2 SB90.2 U5.H1 | length 12
  Top Layer w0.08: 77.225,118.8 77.225,122.572 77.76,123.107 77.76,123.69 77.5,123.95 U5.H1@77.5,125
  Top Layer w0.12: 77.225,118.8 77.225,118.517 77.725,118.017 R25.1@77.725,116.425 R25.1@77.6,116.55
  Bottom Layer w0.12: SB90.2@76.225,115.875 SB89.2@77.725,115.875 v1(77.725,117.05)
PH1: CN10.33 SB88.1 | length 49.8
  Top Layer w0.127: v1(107.577,124.685) CN10.33@109.523,124.685
  Signal Layer 2 w0.12: v1(107.577,124.685) 108.904,123.358 v1(108.904,110.004)
  Bottom Layer w0.12: SB88.1@79.225,114.775 79.225,113.875 79.975,113.125 93.875,113.125 94.425,113.675 97.475,113.675 97.755,113.395 99.798,113.395 99.803,113.4 103.708,113.4 107.108,110 108.9,110 v1(108.904,110.004)
PH1-OSC_OUT: R26.1 SB88.2 U5.J1 | length 10.8
  Top Layer w0.08: 77.465,118.8 77.465,122.578 77.925,123.038 77.925,123.69 ; 77.925,123.701 77.925,123.758 77.676,124.007 77.676,124.676 U5.J1@78,125
  Top Layer w0.12: 77.465,118.8 77.465,118.76 v1(79.225,117) R26.1@79.225,116.425
  Bottom Layer w0.12: SB88.2@79.225,115.875 v1(79.225,117)
PH2: CN9.5 SB20.2 U5.F10 | length 53.7
  Top Layer w0.08: v2(76.25,129.75) U5.F10@76.5,129.5
  Top Layer w0.1: 74.921,136.85 75.346,136.425 v2(76,136.425)
  Top Layer w0.102: v1(37.84,142.465) CN9.5@40.943,142.465
  Top Layer w0.12: v1(68.224,140.824) 71.022,138.025 73.746,138.025 74.921,136.85
  Signal Layer 1 w0.08: v2(76,136.425) 76.365,136.06 76.365,132.802 76.675,132.492 76.675,131.15 76.5,130.975 76.5,130 v2(76.25,129.75)
  Bottom Layer w0.102: SB20.2@36.125,142.45 36.14,142.465 v1(37.84,142.465)
  Bottom Layer w0.12: v1(37.84,142.465) 42.915,142.465 43.775,143.325 53.557,143.325 56.059,140.824 v1(68.224,140.824)
PH3: CN9.7 SB22.2 | length 4.6
  Top Layer w0.12: v1(38.38,141.195) CN9.7@40.943,141.195
  Bottom Layer w0.12: v1(38.38,141.195) 40.095,141.195 SB22.2@40.3,141.4
PH3-BOOT0: JP3.1 R2.2 SB22.1 U5.C5 | length 94.2
  Top Layer w0.08: v2(74.75,126.75) U5.C5@75,127
  Top Layer w0.102: R2.2@34.325,167.3 34.325,164.88 JP3.1@34.33,164.875
  Signal Layer 1 w0.08: v1(67.825,128.9) 67.825,127.668 68.793,126.7 70.202,126.7 70.204,126.702 70.494,126.702 70.496,126.7 74.375,126.7 ; 74.375,126.725 74.4,126.75 v2(74.75,126.75)
  Signal Layer 2 w0.12: v1(52.1,127.55) 52.1,132.95 50.9,134.15 50.9,160.725 52.2,162.025 52.2,163.85 v1(52.186,163.85)
  Bottom Layer w0.1: 66.725,128.5 67.125,128.9 v1(67.825,128.9)
  Bottom Layer w0.12: JP3.1@33.955,164.875 34.35,164.875 35.725,163.5 37.21,163.5 37.56,163.85 v1(52.186,163.85) ; SB22.1@41.4,141.4 42.338,141.4 43.808,142.87 v1(50.9,142.87) ; v1(52.1,127.55) 53.1,127.55 53.585,128.035 54.94,128.035 55.13,127.845 62.12,127.845 62.775,128.5 66.725,128.5
PH4: CN10.13 R178.2 U5.E10 | length 172.6
  Top Layer w0.1: v2(75.75,129.75) U5.E10@76,129.5 ; v1(105.525,137.375) 109.513,137.375 CN10.13@109.523,137.385 111.46,137.385 112.1,138.025 121.1,138.025 121.497,138.422 124.9,138.422 125.1,138.622 125.1,139.05 125.45,139.4 135.05,139.4 135.175,139.275 135.175,139 135.075,138.9 125.675,138.9 125.575,138.8 125.575,138.522 125.675,138.422 141.815,138.422 141.975,138.262 141.975,138.15 141.85,138.025 v1(121.929,138.025)
  Signal Layer 1 w0.08: v1(73.45,133.05) 75.5,131 75.5,130.146 75.5,130 v2(75.75,129.75)
  Signal Layer 2 w0.09: v1(68.225,143.775) 68.225,142.66 68.97,141.915 68.97,139.945 70.822,138.092 71.058,138.092 73.875,135.275 73.875,133.475 v1(73.45,133.05) ; v1(105.1,142.05) 105.1,137.8 v1(105.525,137.375) ; v1(121.929,138.025) 121.929,111.221 121.95,111.2 v1(121.95,109.975)
  Bottom Layer w0.1: v1(68.225,143.775) 85.528,143.775 85.628,143.875 86.975,143.875 88.5,142.35 95.05,142.35 95.35,142.05 v1(105.1,142.05) ; R178.2@120.2,105.05 120.45,105.3 120.45,106.475 120.2,106.725 120.2,109 121.175,109.975 v1(121.95,109.975)
PH5: CN10.14 R145.2 U5.F9 | length 85
  Top Layer w0.1: v2(76.25,129.25) v3(76.5,129) ; v1(112.677,137.385) CN10.14@114.623,137.385
  Signal Layer 1 w0.08: v2(76.25,129.25) v3(76.5,129)
  Signal Layer 2 w0.09: v1(70,150.25) 70,142.616 70.141,142.475 70.141,140.766 71.012,139.896 71.876,139.896 75.371,136.4 76.196,136.4 76.396,136.2 76.396,133.825 76.5,133.721 v3(76.5,129) ; v1(111.522,150.703) 111.522,145.544 111.057,145.079 111.057,139.005 v1(112.677,137.385)
  Bottom Layer w0.1: v1(70,150.25) 70.453,150.703 v1(111.522,150.703) ; v1(112.677,137.385) R145.2@114.14,137.385
  Bottom Layer w0.127: R145.2@114.14,137.385 R145.2@114.15,137.375
PH6: CN10.15 R179.2 U5.E11 | length 170.4
  Top Layer w0.08: v2(75.75,130.25) U5.E11@76,130
  Top Layer w0.12: CN10.15@109.523,136.115 111.715,136.115 112.35,136.75 120.725,136.75 121.175,137.2 140.575,137.2 140.8,136.975 140.8,131.8 140.35,131.35 136.125,131.35 135.975,131.5 135.975,131.75 136.075,131.85 140.225,131.85 140.3,131.925 140.3,132.2 140.2,132.3 136.075,132.3 135.95,132.425 135.95,132.65 136.05,132.75 140.2,132.75 140.3,132.85 140.3,133.1 140.225,133.175 136.075,133.175 135.95,133.3 135.95,133.49 136.085,133.625 140.2,133.625 140.3,133.725 140.3,134 140.2,134.1 136,134.1 135.85,134.25 135.85,134.425 135.987,134.562 139.511,134.562 139.838,134.889 139.838,136.612 139.7,136.75 v1(121.425,136.75)
  Top Layer w0.127: v1(105.415,136.115) CN10.15@109.523,136.115
  Signal Layer 1 w0.08: v2(75.75,130.25) 76,130.5 76,131.175 76.275,131.45 76.275,132.425 75.85,132.85 v1(75.85,134.525)
  Signal Layer 2 w0.12: v1(121.425,111.675) v1(121.425,136.75)
  Bottom Layer w0.12: v1(75.85,134.525) 76.249,134.924 81.325,134.924 81.676,135.275 84.05,135.275 85.05,134.275 99.199,134.275 99.479,133.995 100.895,133.995 103.015,136.115 v1(105.415,136.115) ; R179.2@119.125,105.05 119.075,105.05 117.6,106.525 117.6,109.3 118.075,109.775 120.175,109.775 121.425,111.025 v1(121.425,111.675)
PH7: CN9.41 R239.1 U5.F8 | length 210
  Top Layer w0.08: v2(76.25,128.75) v3(76.5,128.5)
  Top Layer w0.12: v1(16.188,119.4) 18.575,119.4 19.638,120.463 23.675,120.463 ; 42.889,119.605 43.554,120.27 51.205,120.27 51.491,119.984 v1(54.755,119.984)
  Top Layer w0.127: 23.675,120.463 30.812,120.463 31.67,119.605 CN9.41@40.943,119.605 42.889,119.605
  Signal Layer 1 w0.08: v2(76.25,128.75) v3(76.5,128.5)
  Signal Layer 2 w0.08: 76.25,129.275 v2(76.25,128.75) v3(76.5,128.5)
  Signal Layer 2 w0.1: v1(75.75,135.275) 75.475,135 75.475,134.289 76.26,133.504 76.26,129.285 76.25,129.275
  Signal Layer 2 w0.12: v1(54.375,134.75) 54.375,128.175 54.755,127.795 v1(54.755,119.984)
  Signal Layer 2 w0.127: v1(7.658,11.5) 6.563,11.5 5.813,10.75 3.675,10.75 2.942,11.483 2.942,12.517 5.7,15.275 5.7,26.775 0.85,31.625 0.85,87.5 12.5,99.15 12.5,108.25 16.188,111.938 v1(16.188,119.4)
  Bottom Layer w0.1: 66.725,136.713 72.367,136.713 73.031,136.05 74.975,136.05 v1(75.75,135.275)
  Bottom Layer w0.12: v1(54.375,134.75) 61.675,134.75 63.638,136.713 66.725,136.713
  Bottom Layer w0.127: R239.1@7.625,9.775 7.658,9.808 v1(7.658,11.5)
PH8: CN10.16 CN16.31 SB96.1 U5.D12 | length 208.5
  Top Layer w0.08: 75.25,131.65 75.25,130.75 U5.D12@75.5,130.5
  Top Layer w0.1: v1(61.075,135.891) 64.591,135.891 65.2,136.5 72.5,136.5 74.125,134.875 74.125,132.775 75.25,131.65 ; CN10.16@114.623,136.115 v1(116.569,136.115) v1(130.939,136.115) ; CN16.31@116.955,89.66 v1(118.75,89.66)
  Signal Layer 2 w0.09: v1(60.175,152.55) 60.175,146.504 61.075,145.604 v1(61.075,135.891) ; v1(116.569,136.115) 116.979,136.525 116.979,145.546 116.688,145.837 v1(116.688,152.584) ; v1(127.218,89.66) 127.218,105.569 v1(128.6,106.951) 130.398,108.749 130.398,123.638 129.87,124.166 129.87,125.604 130.939,126.673 130.939,135.45 130.5,135.889 130.5,142.825 130.6,142.925 130.85,142.925 130.939,142.836 v1(130.939,136.115)
  Bottom Layer w0.1: v1(60.175,152.55) 90.6,152.55 91.05,152.1 116.205,152.1 v1(116.688,152.584) ; v1(118.75,89.66) 126.425,89.66 126.985,89.1 131.025,89.1 131.1,89.175 131.1,89.535 130.975,89.66 v1(127.218,89.66) ; SB96.1@128.6,105.65 v1(128.6,106.951)
PH13: CN9.8 SB21.2 U5.C12 | length 47.8
  Top Layer w0.08: v1(72.525,135.425) 72.525,133.33 74.75,131.105 74.75,131.104 74.75,130.896 74.75,130.75 U5.C12@75,130.5
  Top Layer w0.127: v1(44.097,141.195) CN9.8@46.043,141.195
  Signal Layer 2 w0.1: 71.1,136.85 v1(72.525,135.425)
  Signal Layer 2 w0.12: v1(44.097,141.195) 44.925,142.023 v1(44.925,145.85) ; v1(68.225,142.1) 68.629,141.696 68.629,139.804 68.837,139.595 68.837,139.113 71.1,136.85
  Bottom Layer w0.12: v1(44.925,145.85) 46.635,144.14 53.71,144.14 55.75,142.1 v1(68.225,142.1)
  Bottom Layer w0.127: v1(44.097,141.195) 45.045,141.195 SB21.2@45.475,141.625
PH15: CN9.9 SB27.2 U5.A13 | length 44.2
  Top Layer w0.08: v1(67.75,135.4) 67.75,135 69.96,132.79 72.21,132.79 U5.A13@74,131
  Top Layer w0.12: v1(38.38,139.925) CN9.9@40.943,139.925 43.025,139.925 43.67,140.57 66.08,140.57 v1(67.75,138.9)
  Signal Layer 2 w0.1: v1(67.75,135.4) v1(67.75,138.9)
  Bottom Layer w0.12: v1(38.38,139.925) 39.925,139.925 SB27.2@40.3,139.55
PI0: CN10.41 SB74.2 U5.B12 | length 143.2
  Top Layer w0.08: v1(67.025,133.925) 67.025,133.484 67.894,132.615 71.91,132.615 73.775,130.75 74.25,130.75 U5.B12@74.5,130.5
  Top Layer w0.127: v1(107.577,119.605) CN10.41@109.523,119.605
  Signal Layer 2 w0.12: v1(52.714,133.912) 52.714,135.174 52.94,135.401 52.94,138.007 53.262,138.329 53.262,149.962 52.376,150.848 52.376,156.776 v1(53.262,157.662) ; v1(105,157.677) 105,153.025 104.299,152.324 104.299,122.883 v1(107.577,119.605)
  Bottom Layer w0.12: v1(52.714,133.912) 62.236,133.912 62.25,133.925 v1(67.025,133.925) ; v1(53.262,157.662) 53.762,158.162 54.77,158.162 55.256,157.677 56.553,157.677 56.557,157.673 90.168,157.673 90.172,157.677 v1(105,157.677) ; SB74.2@106.425,119.6 106.43,119.605 v1(107.577,119.605)
PI1: CN10.5 R177.2 U5.A12 | length 172.8
  Top Layer w0.08: 66.725,133.35 67.625,132.45 71.725,132.45 73.675,130.5 U5.A12@74,130.5
  Top Layer w0.1: v1(62.85,133.514) 66.561,133.514 66.725,133.35 ; v1(107.077,142.512) 109.476,142.512 CN10.5@109.523,142.465 ; CN10.5@109.538,142.45 CN10.5@109.523,142.465 ; v1(131.331,143.1) 138.05,143.1 138.175,143.225 138.175,143.5 138.025,143.65 131.525,143.65 131.35,143.825 131.35,144 131.5,144.15 137.975,144.15 138.1,144.275 138.1,144.525 137.95,144.675 131.05,144.675 130.8,144.425 130.8,143.225 130.675,143.1 111.945,143.1 111.31,142.465 CN10.5@109.523,142.465
  Signal Layer 2 w0.09: v1(62.8,148.725) 62.526,148.451 62.526,145.58 62.85,145.256 v1(62.85,133.514) ; v1(107.077,142.512) v1(107.077,149.452) ; v1(129.875,105.9) 130.786,106.811 130.786,106.971 130.79,106.975 130.79,123.8 130.262,124.328 130.262,125.441 131.331,126.51 131.331,135.856 131.5,136.025 131.5,142.498 131.331,142.667 v1(131.331,143.1)
  Bottom Layer w0.1: v1(62.8,148.725) 62.808,148.733 70.383,148.733 71.102,149.452 v1(107.077,149.452) ; R177.2@129.875,105.05 v1(129.875,105.9)
PI2: CN10.6 CN16.17 SB101.1 U5.D11 | length 204.3
  Top Layer w0.1: v2(75.25,130.25) U5.D11@75.5,130 ; v1(112.275,142.465) CN10.6@114.623,142.465 v1(122.325,142.465) ; CN16.17@116.95,82.655 117.08,82.525 v1(118.5,82.525)
  Signal Layer 1 w0.08: v1(71.725,135.075) 72.1,134.7 72.1,133.902 75.25,130.752 v2(75.25,130.25)
  Signal Layer 2 w0.09: v1(68.114,146.539) 67.796,146.221 67.796,140.154 68.496,139.454 68.496,138.887 70.584,136.799 70.626,136.799 71.725,135.7 v1(71.725,135.075) ; v1(112.275,142.465) 112.275,142.9 113.319,143.944 v1(113.319,148.618) ; v1(121.425,106.695) 122,106.12 122,102.475 123.3,101.175 123.3,100.025 122.789,99.514 122.789,83.036 v1(123.3,82.525) ; v1(122.325,111.775) 122.325,141.643 122.582,141.9 123.05,141.9 123.425,142.275 123.425,155.025 123.325,155.125 123.2,155.125 123.1,155.025 123.1,142.6 122.975,142.475 122.85,142.475 122.75,142.575 122.75,155.15 122.625,155.275 122.45,155.275 122.325,155.15 v1(122.325,142.465)
  Bottom Layer w0.1: v1(68.114,146.539) 68.993,147.418 ; 68.975,147.4 68.993,147.418 91.023,147.418 92.223,148.618 v1(113.319,148.618) ; v1(118.5,82.525) v1(123.3,82.525) ; SB101.1@121.425,105.65 v1(121.425,106.695) 122.75,108.02 122.75,111.35 v1(122.325,111.775)
PI3: CN10.7 CN16.19 SB98.1 U5.D10 | length 208.2
  Top Layer w0.1: v2(75.25,129.75) U5.D10@75.5,129.5 ; v1(106.25,141.195) CN10.7@109.523,141.195 111.82,141.195 112.45,141.825 128.725,141.825 129.075,141.475 129.075,140.7 129.375,140.4 139.175,140.4 139.275,140.5 139.275,140.775 139.175,140.875 129.65,140.875 129.525,141 129.525,141.225 129.675,141.375 139.175,141.375 139.275,141.475 139.275,141.725 139.175,141.825 v1(129.458,141.825) ; CN16.19@116.955,83.66 v1(118.75,83.66)
  Signal Layer 1 w0.08: v1(71.1,135.525) 71.1,135.2 71.75,134.55 71.75,133.95 75,130.7 75,130.4 75,130 v2(75.25,129.75)
  Signal Layer 2 w0.09: v1@68.25,148.365 v1(68.25,148.3) 68.25,147.243 66.925,145.919 66.925,135.694 67.609,135.01 69.31,135.01 69.825,135.525 v1(71.1,135.525) ; v1(106.25,141.195) v1(106.25,149.035) ; v1(126.425,83.825) 126.425,87.623 126.426,87.624 125.529,88.521 125.529,94.464 125.725,94.66 v1(125.725,106.951) 129.614,110.84 129.614,122.652 128.662,123.605 128.662,125.504 129.458,126.3 v1(129.458,141.825)
  Bottom Layer w0.1: v1(68.25,148.3) 70.55,148.3 71.285,149.035 v1(106.25,149.035) ; v1(118.75,83.66) 122.05,83.66 122.215,83.825 v1(126.425,83.825) ; SB98.1@125.725,105.65 v1(125.725,106.951)
PI5: CN10.9 CN16.32 SB112.1 U5.B3 | length 209.4
  Top Layer w0.08: 72.983,125.325 73.408,125.75 74.25,125.75 U5.B3@74.5,126
  Top Layer w0.1: v1(64.85,125.2) 65.5,125.85 68.325,125.85 68.86,125.315 72.973,125.315 72.983,125.325 ; v1(105.55,139.925) CN10.9@109.523,139.925 ; v1(112.31,89.655) CN16.32@114.4,89.655
  Signal Layer 2 w0.09: v1(64.85,125.2) 64.161,125.889 64.161,142.968 63.765,143.364 63.765,145.665 65.066,146.966 65.066,148.754 65.462,149.15 v1(65.462,149.962) ; v1(105.55,150.286) v1(105.55,139.925) 105.921,139.554 105.921,133.521 104.7,132.3 104.7,123.081 108,119.781 108,106.225 107.352,105.577 107.352,88.173 107.45,88.075 107.625,88.075 107.75,88.2 107.75,105.475 107.85,105.575 108,105.575 108.125,105.45 108.125,89.725 108.225,89.625 108.425,89.625 108.525,89.725 108.525,99.625 108.6,99.7 108.9,99.7 108.975,99.625 108.975,89.625 108.425,89.075 v1(108.425,88.025)
  Bottom Layer w0.1: v1(65.462,149.962) 65.682,149.742 70.177,149.742 70.722,150.286 v1(105.55,150.286) ; v1(108.425,88.025) 110.25,88.025 111.1,88.875 111.1,89.75 ; SB112.1@110.925,89.925 111.1,89.75 ; 111.1,89.875 111.1,89.75 ; v1(112.31,89.655) 111.195,89.655 111.1,89.75
PMOD#1: CN3.1 CN7.1 U1.8 | length 31.3
  Top Layer w0.12: U1.8@120.175,158.225 121.546,158.225 v1(121.95,157.821) ; CN3.1@130.1,157.821 133.296,154.625 138.302,154.625 138.827,154.1 v1(144.8,154.1)
  Signal Layer 2 w0.1: CN7.1@144.8,149.128 144.8,150.3
  Signal Layer 2 w0.12: 144.8,150.3 v1(144.8,154.1)
  Bottom Layer w0.12: v1(121.95,157.821) CN3.1@130.1,157.821
PMOD#2: CN3.2 CN7.2 U1.16 | length 38.4
  Top Layer w0.12: v1(118.225,162.075) 118.225,161.4 118.975,160.65 U1.16@118.975,160.575 ; CN3.2@132.64,157.821 135.211,155.25 138.827,155.25 139.352,154.725 v1(143.8,154.725)
  Signal Layer 2 w0.1: 143.8,150.3 143.8,148.128 CN7.2@144.8,147.128
  Signal Layer 2 w0.12: 143.8,150.3 v1(143.8,154.725)
  Bottom Layer w0.12: v1(118.225,162.075) 123.675,162.075 126.625,159.125 131.336,159.125 CN3.2@132.64,157.821
PMOD#3: CN3.3 CN7.3 U1.5 | length 40.2
  Top Layer w0.12: v1(117.845,156.855) 117.845,157.37 118.275,157.8 118.55,157.8 U1.5@118.975,158.225 ; CN3.3@135.18,157.821 136.646,156.355 139.845,156.355 140.405,155.795 v1(143.395,155.795)
  Signal Layer 2 w0.1: 143.525,146.403 CN7.3@144.8,145.128
  Signal Layer 2 w0.12: v1(143.395,155.795) 143.395,146.533 143.525,146.403
  Bottom Layer w0.12: v1(117.845,156.855) 123.02,156.855 123.271,156.604 133.963,156.604 CN3.3@135.18,157.821
PMOD#4: CN3.4 CN7.4 U1.13 | length 43.2
  Top Layer w0.12: U1.13@120.175,160.575 120.9,161.3 v1(121.45,161.3) ; CN3.4@137.72,157.821 138.85,156.691 139.959,156.691 140.275,156.375 v1(142.99,156.375)
  Signal Layer 2 w0.1: 143.525,144.403 CN7.4@144.8,143.128
  Signal Layer 2 w0.12: v1(121.45,156.45) v1(121.45,161.3) ; v1(142.99,156.375) 142.99,144.938 143.525,144.403
  Bottom Layer w0.12: v1(121.45,156.45) 122.964,156.45 123.05,156.364 136.263,156.364 CN3.4@137.72,157.821
RFU1: CN5.14 TP4.1 | length 25.1
  Top Layer w0.12: CN5.14@129.45,148.025 129.45,149.05 130.341,149.941 142.191,149.941 143.55,151.3 147.5,151.3 TP4.1@151.1,154.9
RFU2: CN5.13 TP1.1 | length 27.5
  Top Layer w0.15: CN5.13@129.45,152.525 129.45,151.477 130.092,150.835 141.989,150.835 143.424,152.27 144.295,152.27 149.2,157.175 149.2,158.325 TP1.1@151.1,160.225
RSTOUTn: CN5.15 TP2.1 | length 27.3
  Top Layer w0.13: CN5.15@128.65,152.525 128.65,151.2 129.275,150.575 142.097,150.575 143.532,152.01 144.66,152.01 TP2.1@151.1,158.45
SAI1_FS_B: SB62.2 U25.1 | length 191.6
  Top Layer w0.12: v1(115.5,35.425) 118.2,35.425 119.65,36.875 U25.1@119.65,37.075
  Signal Layer 2 w0.12: v1(30.375,123.414) 30.375,106.35 26.5,102.475 26.5,76.2 36.375,66.325 v1(36.375,37.475)
  Bottom Layer w0.12: v1(30.375,123.414) SB62.2@40.317,123.414 ; v1(36.375,37.475) 62.025,37.475 66.195,33.305 83.995,33.305 88.025,29.275 108.6,29.275 114.75,35.425 v1(115.5,35.425)
SAI1_MCLK_B: R154.2 U25.30 | length 180.9
  Top Layer w0.102: v1(113.485,36.9) 116.375,36.9 118.225,38.75 U25.30@118.975,38.75
  Signal Layer 2 w0.12: v1(31.375,125.525) 31.375,106.2 27.25,102.075 27.25,76.45 37.35,66.35 v1(37.35,38.975)
  Bottom Layer w0.102: v1(37.35,38.975) 38.754,38.975 38.825,38.904 63.221,38.904 66.45,35.675 77.85,35.675 78.265,35.26 101.31,35.26 102.95,36.9 v1(113.485,36.9)
  Bottom Layer w0.12: v1(31.375,125.525) 32.65,125.525 33.175,126.05 R154.2@35.05,126.05
SAI1_SCK_B: R157.2 U25.31 | length 181.4
  Top Layer w0.102: v1(114.175,36.5) 116.7,36.5 118.45,38.25 U25.31@118.975,38.25
  Signal Layer 2 w0.12: v1(30.875,124.625) 30.875,106.25 26.925,102.3 26.925,76.3 36.8,66.425 v1(36.8,38.407)
  Bottom Layer w0.102: v1(36.8,38.407) 63.218,38.407 66.375,35.25 77.575,35.25 78.275,34.55 112.225,34.55 v1(114.175,36.5)
  Bottom Layer w0.12: v1(30.875,124.625) R157.2@35.05,124.625
SAI1_SDIN_B: R153.2 U25.32 | length 186.2
  Top Layer w0.102: v1(114.8,36.1) 117.1,36.1 118.75,37.75 U25.32@118.975,37.75
  Signal Layer 2 w0.12: v1(31.85,126.5) 31.85,106.2 27.595,101.945 27.595,76.555 37.845,66.305 v1(37.845,37.925)
  Bottom Layer w0.102: v1(37.845,37.925) 62.95,37.925 67.275,33.6 84.7,33.6 88.7,29.6 108.3,29.6 v1(114.8,36.1)
  Bottom Layer w0.12: v1(31.85,126.5) 32.85,127.5 R153.2@35.05,127.5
